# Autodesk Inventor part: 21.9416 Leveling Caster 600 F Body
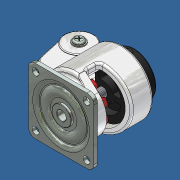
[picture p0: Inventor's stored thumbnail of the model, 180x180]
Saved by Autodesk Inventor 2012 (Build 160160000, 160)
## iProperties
Created: 2015-01
Part Number: 21.9416 Leveling Caster 600 F Body
Material: Default
Document SubType Name: Modeling
Designer: Admin
Density: 3.66292 g/cm^3
Mass: 1360.78 g
Surface Area: 1096.09 cm^2
Volume: 371.5 cm^3
Author: Admin
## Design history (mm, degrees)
feature "Base1"
body "Solid1"
